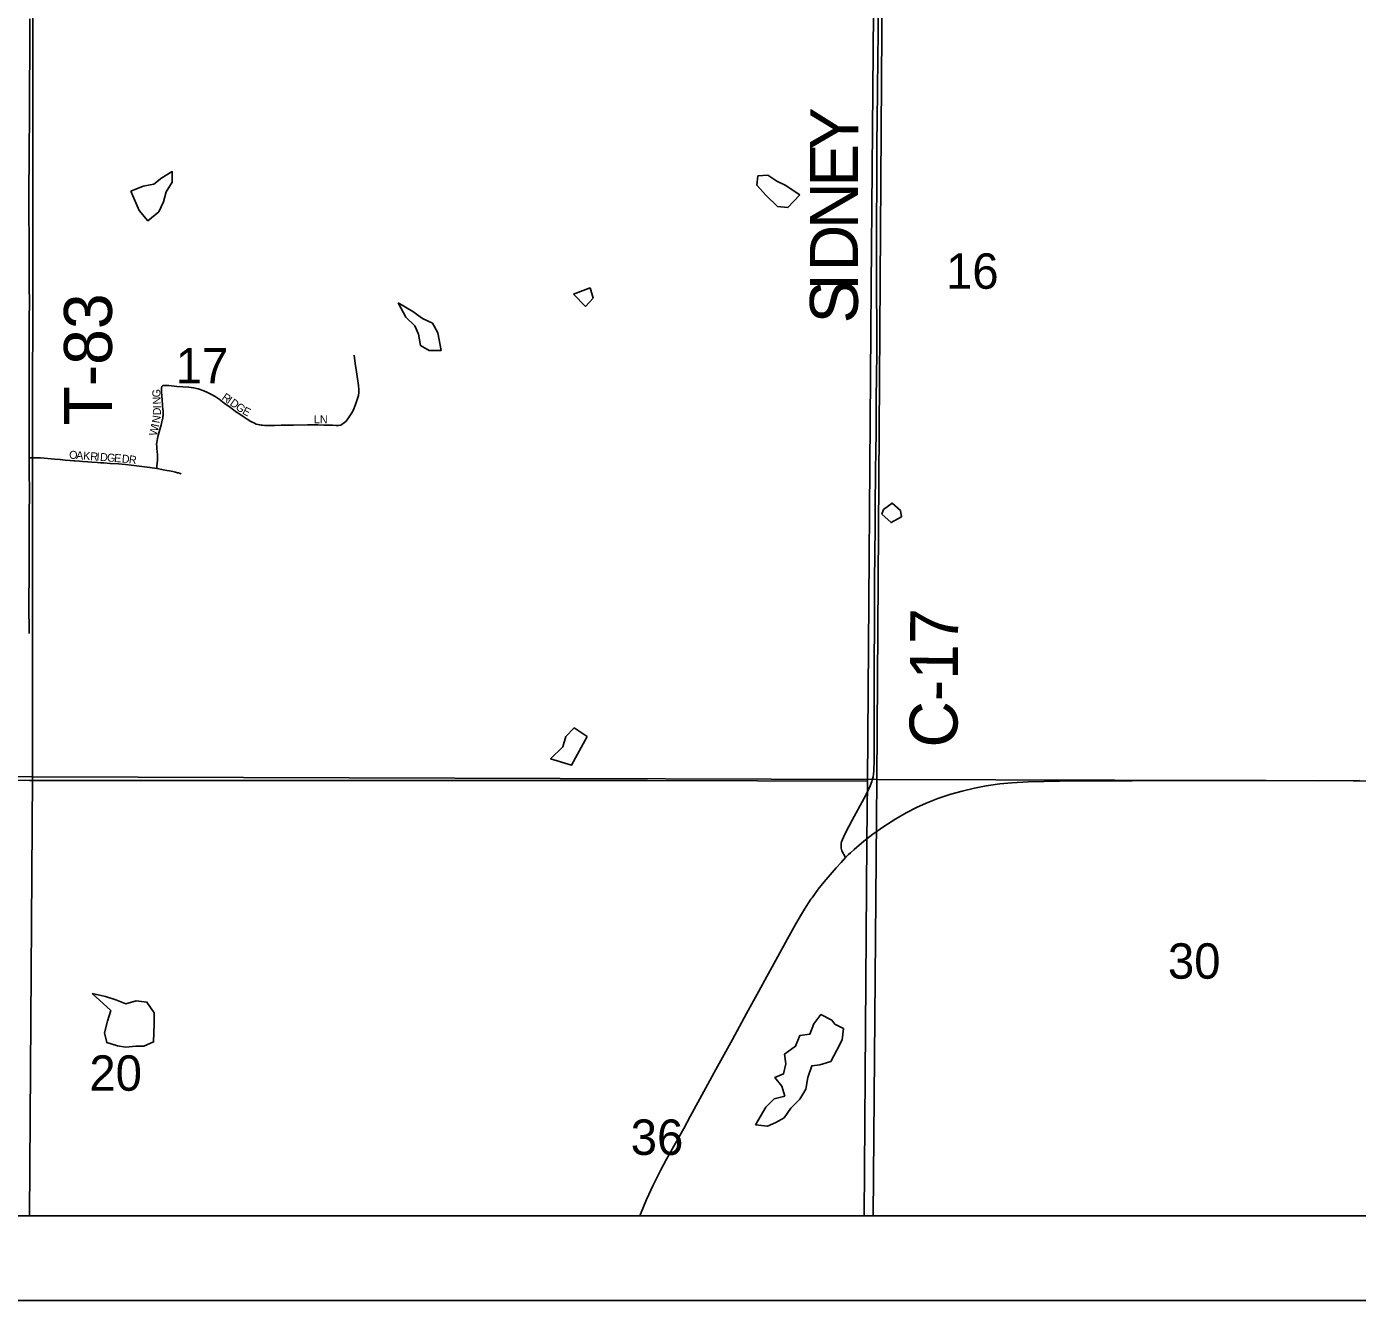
# Model space of a CAD drawing. Extents: x -784 to 1375, y -225 to 440.
# Drawn here: x 519.27 to 550.75, y 281.31 to 311.43 of the extents above; entities that cross this region are included whole.
import ezdxf

# ---------------------------------------------------------------- set-up
doc = ezdxf.new("R2010")
doc.units = 0
for name, color, linetype in [('GM_X_County_Road', 7, 'Continuous'), ('GM_X_County_Road_Text', 7, 'Continuous'), ('GM_X_Minor_Lake', 7, 'Continuous'), ('GM_X_Section', 7, 'Continuous'), ('GM_X_Section_Text', 7, 'Continuous'), ('GM_X_State_Route', 7, 'Continuous'), ('GM_X_Township', 7, 'Continuous'), ('GM_X_Township_Road', 7, 'Continuous'), ('GM_X_Township_Road_Text', 7, 'Continuous'), ('GM_X_Township_Subdivision', 7, 'Continuous'), ('GM_X_Township_Subdivision_Text', 7, 'Continuous'), ('SH_Data', 7, 'Continuous')]:
    doc.layers.add(name, color=color, linetype=linetype)

msp = doc.modelspace()

# ---------------------------------------------------------------- linework, layer by layer
at = {"layer": 'GM_X_County_Road'}
for points in [[(539.39, 309.166), (539.396, 309.968), (539.412, 311.322), (539.418, 312.316), (539.423, 313.272), (539.425, 313.37)], [(539.38, 304.502), (539.377, 305.018), (539.374, 306.31), (539.379, 306.732), (539.381, 307.801), (539.387, 308.733), (539.39, 309.166)], [(539.385, 303.721), (539.38, 304.502)], [(539.377, 303.161), (539.385, 303.721)], [(539.328, 297.768), (539.33, 298.332), (539.346, 299.586), (539.342, 300.034), (539.353, 300.941), (539.366, 301.822), (539.37, 302.63), (539.377, 303.161)], [(539.323, 295.55), (539.322, 295.897), (539.328, 297.768)], [(539.266, 293.581), (539.283, 293.642), (539.294, 293.691), (539.303, 293.756), (539.311, 293.834), (539.314, 293.922), (539.318, 293.996), (539.323, 294.617), (539.323, 295.55)], [(538.644, 291.78), (538.558, 291.939), (538.545, 291.973), (538.539, 292.006), (538.536, 292.04), (538.537, 292.077), (538.541, 292.115), (538.549, 292.154), (538.571, 292.209), (538.621, 292.317), (538.721, 292.514), (538.804, 292.668), (539.082, 293.183), (539.168, 293.35), (539.227, 293.475), (539.266, 293.581)]]:
    msp.add_lwpolyline(points, dxfattribs=at)
at = {"layer": 'GM_X_Minor_Lake'}
for p, q in [((522.569, 307.522), (522.71, 307.754)), ((536.57, 307.902), (536.544, 307.683)), ((532.674, 305.006), (532.602, 305.258)), ((539.544, 300.01), (539.504, 299.905)), ((539.967, 299.835), (539.946, 299.987)), ((538.39, 287.839), (538.316, 287.939))]:
    msp.add_line(p, q, dxfattribs=at)
for points in [[(522.71, 307.754), (522.714, 308.004), (522.468, 307.857), (522.276, 307.702), (522.024, 307.662), (521.735, 307.544)], [(537.565, 307.457), (537.213, 307.684), (537.017, 307.779), (536.806, 307.92), (536.57, 307.902)], [(536.544, 307.683), (536.767, 307.436), (537.037, 307.18), (537.279, 307.152), (537.565, 307.457)], [(521.735, 307.544), (521.93, 307.08), (522.139, 306.841), (522.394, 307.048), (522.504, 307.288), (522.569, 307.522)], [(532.602, 305.258), (532.207, 305.102)], [(532.207, 305.102), (532.495, 304.813), (532.674, 305.006)], [(528.062, 304.903), (528.242, 304.561), (528.451, 304.359), (528.539, 304.16), (528.588, 303.887), (528.791, 303.769), (529.076, 303.774)], [(529.076, 303.774), (528.996, 304.189), (528.87, 304.419), (528.637, 304.53), (528.404, 304.694), (528.062, 304.903)], [(539.946, 299.987), (539.744, 300.165), (539.544, 300.01)], [(539.504, 299.905), (539.721, 299.703), (539.967, 299.835)], [(532.528, 294.642), (532.22, 294.848), (532.026, 294.64), (531.954, 294.399), (531.66, 294.116)], [(531.66, 294.116), (532.16, 293.962), (532.528, 294.642)], [(520.819, 288.569), (521.261, 288.161), (521.181, 287.912), (521.108, 287.633), (521.165, 287.404), (521.422, 287.331), (521.619, 287.296), (521.855, 287.322), (522.045, 287.318), (522.275, 287.419), (522.289, 287.851)], [(522.289, 287.851), (522.286, 288.109), (522.116, 288.363), (521.865, 288.391), (521.613, 288.32), (521.379, 288.416), (521.137, 288.497), (520.819, 288.569)], [(538.316, 287.939), (538.059, 288.066), (537.896, 287.849), (537.801, 287.601), (537.565, 287.575), (537.462, 287.319), (537.2, 287.135), (537.227, 286.9), (537.177, 286.665), (536.971, 286.579), (537.134, 286.378), (537.207, 286.141), (536.955, 286.071), (536.754, 285.878), (536.517, 285.46)], [(536.517, 285.46), (536.799, 285.429), (536.991, 285.516), (537.19, 285.626), (537.346, 285.858), (537.563, 286.066), (537.703, 286.305), (537.754, 286.577), (537.842, 286.856), (538.032, 286.875), (538.292, 286.961), (538.441, 287.223), (538.567, 287.471), (538.594, 287.736), (538.39, 287.839)]]:
    msp.add_lwpolyline(points, dxfattribs=at)
at = {"layer": 'GM_X_Section'}
for p, q in [((499.224, 283.309), (519.336, 283.309)), ((519.336, 283.309), (539.3, 283.309)), ((539.3, 283.309), (554.103, 283.309))]:
    msp.add_line(p, q, dxfattribs=at)
for points in [[(519.411, 314.122), (519.42, 313.796), (519.407, 293.691), (499.2, 293.85), (499.543, 314.191)], [(519.42, 313.796), (539.515, 313.692), (539.382, 293.628), (519.407, 293.691)], [(539.515, 313.692), (559.175, 313.642), (559.1, 293.569), (539.382, 293.628)]]:
    msp.add_lwpolyline(points, close=True, dxfattribs=at)
for points in [[(519.336, 283.309), (519.407, 293.691), (499.2, 293.85), (499.224, 283.309)], [(539.3, 283.309), (539.382, 293.628), (519.407, 293.691), (519.336, 283.309)], [(559.1, 293.569), (539.382, 293.628), (539.3, 283.309)]]:
    msp.add_lwpolyline(points, dxfattribs=at)
at = {"layer": 'GM_X_State_Route'}
for points in [[(538.715, 291.851), (538.758, 291.894), (538.847, 291.972), (539.075, 292.167), (539.222, 292.281), (539.292, 292.335), (539.547, 292.513), (539.83, 292.695), (540.079, 292.838), (540.323, 292.964), (540.55, 293.065), (540.829, 293.174), (541.137, 293.277), (541.4, 293.353), (541.691, 293.423), (541.973, 293.477), (542.293, 293.522), (542.579, 293.55), (542.964, 293.571), (543.709, 293.589), (544.567, 293.596), (545.424, 293.599), (545.934, 293.603), (546.803, 293.6), (547.723, 293.605), (548.292, 293.607), (548.593, 293.605), (549.823, 293.599), (550.805, 293.602)], [(537.85, 290.829), (537.993, 291.03), (538.095, 291.158), (538.183, 291.263), (538.418, 291.537), (538.538, 291.665), (538.644, 291.78), (538.715, 291.851)], [(537.49, 290.251), (537.578, 290.404), (537.672, 290.557), (537.825, 290.795), (537.85, 290.829)], [(536.679, 288.776), (536.698, 288.81), (536.997, 289.351), (537.27, 289.856), (537.469, 290.214), (537.49, 290.251)], [(536.297, 288.094), (536.679, 288.776)], [(535.967, 287.48), (536.297, 288.094)], [(535.288, 286.248), (535.575, 286.771), (535.967, 287.48)], [(534.968, 285.659), (535.288, 286.248)], [(534.41, 284.646), (534.814, 285.375), (534.968, 285.659)], [(533.779, 283.309), (533.807, 283.387), (533.933, 283.698), (534.09, 284.035), (534.266, 284.378), (534.41, 284.646)]]:
    msp.add_lwpolyline(points, dxfattribs=at)
at = {"layer": 'GM_X_Township'}
msp.add_line((458.267, 283.309), (539.084, 283.309), dxfattribs=at)
for points in [[(539.731, 361.675), (539.664, 353.833), (539.563, 342.208), (539.492, 333.882), (539.39, 322.02), (539.32, 313.642), (539.251, 305.289), (539.16, 293.586), (533.956, 293.601), (527.265, 293.606), (519.34, 293.604), (517.829, 293.627)], [(539.32, 313.642), (539.251, 305.289), (539.16, 293.586), (539.15, 292.161), (539.084, 283.309), (554.071, 283.309)], [(539.084, 283.309), (539.15, 292.161), (539.16, 293.586), (533.956, 293.601), (527.265, 293.606), (519.34, 293.604), (517.829, 293.627), (516.502, 293.627), (514.346, 293.626), (507.742, 293.624), (496.837, 293.807), (490.416, 293.843), (485.23, 293.95), (481.696, 294.072), (478.992, 294.22), (476.854, 294.139), (474.329, 294.056), (470.984, 294.092), (462.46, 294.056), (458.296, 294.134), (458.263, 284.231), (458.267, 283.309)]]:
    msp.add_lwpolyline(points, dxfattribs=at)
at = {"layer": 'GM_X_Township_Road'}
for points in [[(519.333, 301.237), (519.329, 301.37), (519.329, 301.767), (519.329, 302.659), (519.327, 302.969), (519.329, 303.229), (519.332, 303.565), (519.33, 303.776), (519.327, 303.962), (519.331, 304.522), (519.334, 304.907), (519.333, 305.292), (519.333, 305.627), (519.332, 306.224), (519.329, 306.41), (519.324, 306.994), (519.324, 307.28), (519.325, 307.777), (519.326, 308.087), (519.331, 308.683), (519.336, 309.143), (519.339, 309.64), (519.341, 310.075), (519.345, 310.734), (519.345, 311.367), (519.344, 311.615)], [(519.329, 299.87), (519.334, 300.412), (519.332, 300.934), (519.333, 301.237)], [(519.327, 298.323), (519.33, 299.392), (519.329, 299.852), (519.329, 299.87)], [(519.325, 297.769), (519.325, 297.989), (519.327, 298.323)], [(519.326, 297.076), (519.325, 297.769)]]:
    msp.add_lwpolyline(points, dxfattribs=at)
at = {"layer": 'GM_X_Township_Subdivision'}
for points in [[(522.347, 300.979), (522.353, 301.04), (522.367, 301.179), (522.367, 301.247), (522.364, 301.304), (522.357, 301.386), (522.353, 301.45), (522.349, 301.5), (522.346, 301.557), (522.35, 301.6), (522.367, 301.689), (522.385, 301.765), (522.407, 301.849), (522.438, 301.958), (522.451, 302.005), (522.48, 302.125), (522.481, 302.137), (522.489, 302.173), (522.493, 302.208), (522.497, 302.233), (522.5, 302.292), (522.499, 302.325), (522.498, 302.336), (522.497, 302.346), (522.494, 302.386), (522.487, 302.465), (522.483, 302.514), (522.479, 302.575), (522.478, 302.6), (522.47, 302.697), (522.459, 302.784), (522.459, 302.836), (522.459, 302.88), (522.47, 302.923), (522.495, 302.945), (522.57, 302.948), (522.636, 302.941), (522.823, 302.923), (522.966, 302.913), (523.105, 302.906), (523.219, 302.892), (523.326, 302.867), (523.458, 302.82), (523.551, 302.778), (523.629, 302.737), (523.728, 302.681), (523.822, 302.618), (523.942, 302.528), (524.089, 302.425), (524.211, 302.332), (524.311, 302.265), (524.389, 302.211), (524.439, 302.179), (524.489, 302.147), (524.576, 302.093), (524.661, 302.052), (524.703, 302.033), (524.75, 302.02), (524.784, 302.013), (524.818, 302.008), (524.853, 302.003), (524.903, 302.001), (524.949, 302.001), (525.02, 302.001), (525.078, 302.001), (525.138, 302.001), (525.288, 302.005), (525.432, 302.004), (525.581, 302.01), (525.915, 302.015), (526.155, 302.012), (526.304, 302.009), (526.422, 302.006), (526.508, 302.006), (526.593, 302.002), (526.65, 302.002), (526.7, 302.009), (526.737, 302.029), (526.757, 302.043), (526.792, 302.072), (526.82, 302.094), (526.85, 302.131), (526.886, 302.177), (526.918, 302.224), (526.96, 302.295), (526.993, 302.352), (527.05, 302.496), (527.099, 302.636), (527.118, 302.706), (527.127, 302.777), (527.129, 302.85), (527.122, 302.947), (527.075, 303.265), (527.046, 303.461), (527.021, 303.658)], [(519.333, 301.237), (519.597, 301.234), (519.933, 301.206), (520.067, 301.195), (520.116, 301.189), (520.128, 301.188), (520.185, 301.182), (520.295, 301.174), (520.386, 301.166), (520.411, 301.164), (520.517, 301.157), (520.598, 301.151), (520.718, 301.14), (520.815, 301.131), (520.949, 301.122), (521.016, 301.118), (521.073, 301.114), (521.097, 301.112), (521.248, 301.103), (521.44, 301.089), (521.611, 301.075), (521.743, 301.061), (521.936, 301.036), (522.186, 301.007), (522.347, 300.979)], [(522.347, 300.979), (522.394, 300.971), (522.503, 300.95), (522.585, 300.937), (522.653, 300.923), (522.731, 300.908), (522.788, 300.894), (522.84, 300.882), (522.861, 300.877), (522.9, 300.865), (522.922, 300.859)]]:
    msp.add_lwpolyline(points, dxfattribs=at)
at = {"layer": 'SH_Data'}
for p, q in [((444.236, 283.309), (580.236, 283.309)), ((442.236, 281.309), (581.184, 281.309))]:
    msp.add_line(p, q, dxfattribs=at)

# ---------------------------------------------------------------- texts
at = {"layer": 'GM_X_County_Road_Text'}
for s, height, rotation, p in [('Y', 1.136, 89.1548, (538.936, 308.494)), ('E', 1.136, 89.9743, (538.936, 307.648)), ('N', 1.136, 90, (538.936, 306.648)), ('D', 1.136, 90, (538.936, 305.648)), ('I', 1.136, 90, (538.936, 305.181)), ('S', 1.136, 90, (538.936, 304.415)), ('C-17', 1.1364, 89.657, (541.291, 294.38))]:
    msp.add_text(s, height=height, rotation=rotation, dxfattribs=at).set_placement(p)
at = {"layer": 'GM_X_Section_Text'}
for s, p in [('16', (541.02, 305.232)), ('17', (522.795, 302.993)), ('30', (546.27, 288.916)), ('20', (520.753, 286.266)), ('36', (533.561, 284.749))]:
    msp.add_text(s, height=0.8371, rotation=0, dxfattribs=at).set_placement(p)
at = {"layer": 'GM_X_Township_Road_Text'}
msp.add_text('T-83', height=1.1364, rotation=90, dxfattribs=at).set_placement((521.289, 301.998))
at = {"layer": 'GM_X_Township_Subdivision_Text'}
for s, height, rotation, p in [('G', 0.189, 91.9456, (522.437, 302.667)), ('N', 0.189, 93.3544, (522.446, 302.502)), ('R', 0.189, 324.7136, (523.871, 302.627)), ('I', 0.189, 324.7035, (523.993, 302.54)), ('D', 0.189, 324.7074, (524.062, 302.492)), ('D', 0.189, 89.2945, (522.445, 302.238)), ('I', 0.189, 90.4075, (522.447, 302.408)), ('G', 0.189, 324.7037, (524.198, 302.396)), ('E', 0.189, 332.453, (524.358, 302.285)), ('LN', 0.1894, 0, (526.067, 302.05)), ('W', 0.189, 77.6481, (522.348, 301.739)), ('I', 0.189, 77.6182, (522.395, 301.95)), ('N', 0.189, 80.3531, (522.415, 302.041)), ('O', 0.189, 355.7555, (520.27, 301.217)), ('A', 0.189, 355.7337, (520.436, 301.205)), ('K', 0.189, 355.759, (520.602, 301.192)), ('R', 0.189, 355.7466, (520.768, 301.18)), ('I', 0.189, 355.7441, (520.918, 301.169)), ('D', 0.189, 355.7337, (521.001, 301.163)), ('G', 0.189, 355.759, (521.167, 301.15)), ('E', 0.189, 355.7333, (521.334, 301.138)), ('D', 0.189, 354.5047, (521.515, 301.124)), ('R', 0.189, 352.5225, (521.68, 301.109))]:
    msp.add_text(s, height=height, rotation=rotation, dxfattribs=at).set_placement(p)

doc.saveas('drawing.dxf')
